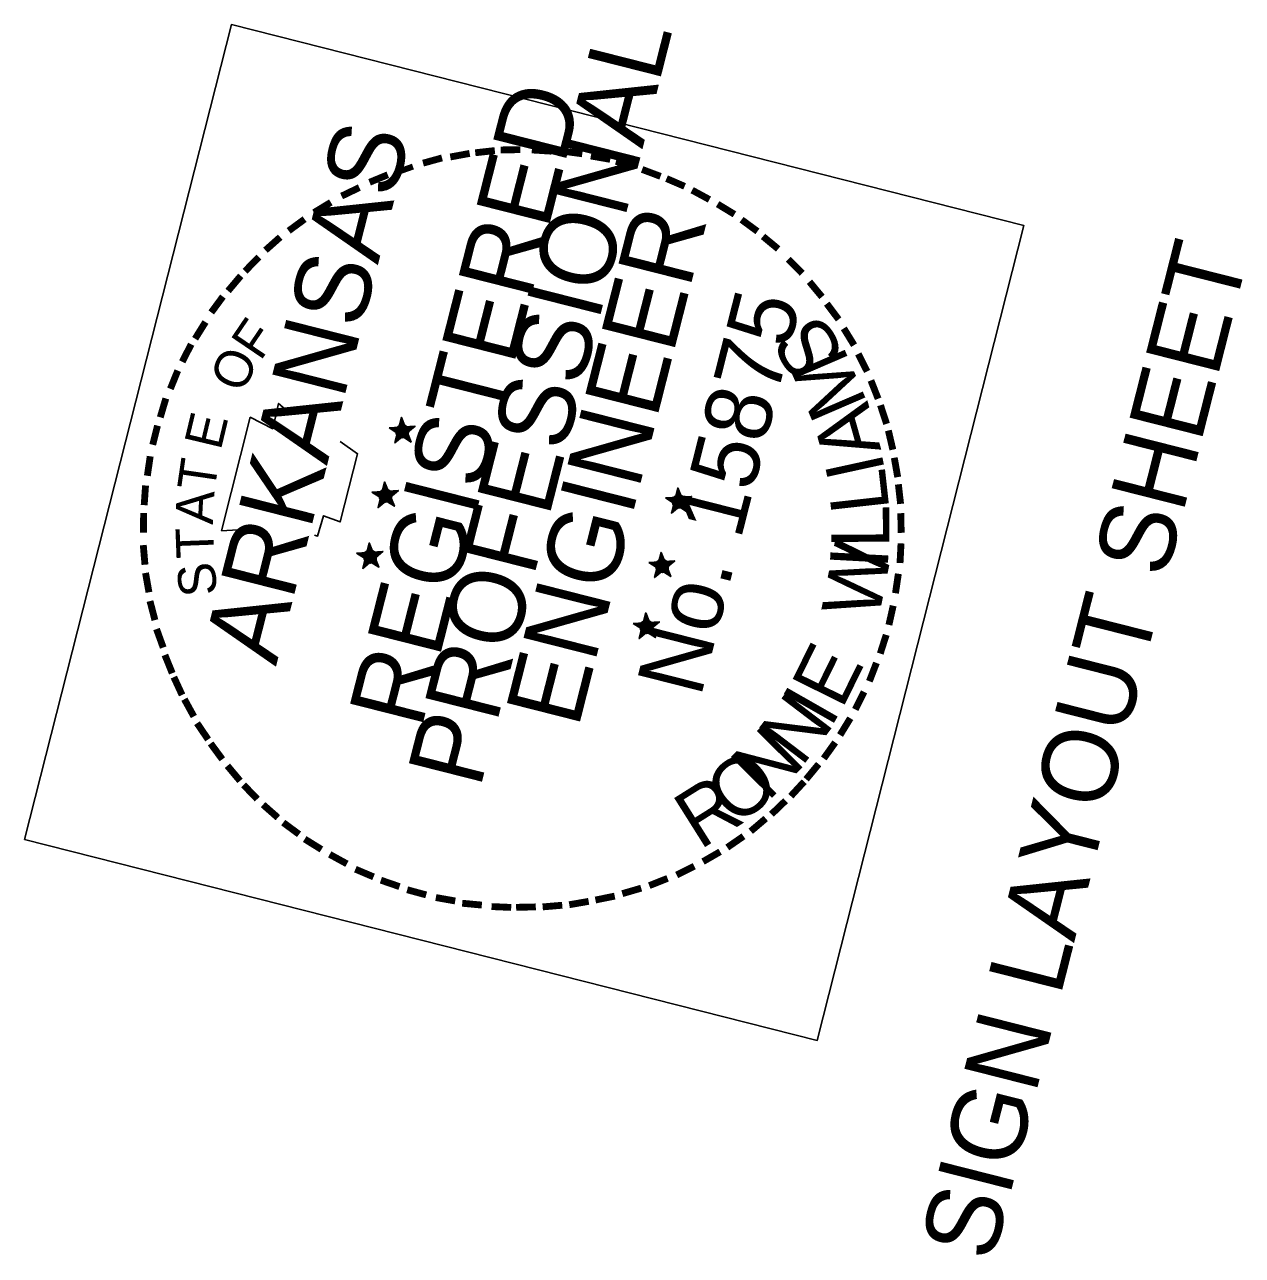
# Model space of a CAD drawing. Extents: x 670002 to 670131, y 737831 to 738002.
# Drawn here: x 670110.58 to 670130.78, y 737963.35 to 737983.77 of the extents above; entities that cross this region are included whole.
import ezdxf

# ---------------------------------------------------------------- set-up
doc = ezdxf.new("R2010")
doc.units = 0
for name, color, linetype in [('R_Border Notes', 7, 'Continuous'), ('R_Border PE', 7, 'Continuous'), ('R_Border Prem', 7, 'Continuous')]:
    doc.layers.add(name, color=color, linetype=linetype)

msp = doc.modelspace()

# ---------------------------------------------------------------- linework, layer by layer
at = {"layer": 'R_Border PE'}
for p, q in [((670116.623, 737977.081), (670116.785, 737977.085)), ((670116.841, 737977.025), (670116.623, 737977.081)), ((670116.623, 737977.081), (670116.782, 737977.073)), ((670116.623, 737977.081), (670116.772, 737977.056)), ((670116.623, 737977.081), (670116.772, 737977.03)), ((670116.623, 737977.081), (670116.769, 737977.018)), ((670116.623, 737977.081), (670116.759, 737977.007)), ((670116.828, 737977.254), (670116.793, 737977.063)), ((670116.828, 737977.254), (670116.814, 737977.071)), ((670116.828, 737977.254), (670116.826, 737977.068)), ((670116.828, 737977.254), (670116.841, 737977.025)), ((670116.828, 737977.254), (670116.849, 737977.107)), ((670116.828, 737977.254), (670116.857, 737977.112)), ((670116.828, 737977.254), (670116.866, 737977.122)), ((670117.055, 737977.106), (670116.841, 737977.025)), ((670117.055, 737977.106), (670116.86, 737977.072)), ((670117.055, 737977.106), (670116.863, 737977.084)), ((670117.055, 737977.106), (670116.882, 737977.06)), ((670117.055, 737977.106), (670116.89, 737977.013)), ((670117.055, 737977.106), (670116.902, 737977.036)), ((670117.055, 737977.106), (670116.908, 737977.008)), ((670116.721, 737976.83), (670116.841, 737977.025)), ((670116.721, 737976.83), (670116.779, 737976.983)), ((670116.721, 737976.83), (670116.79, 737976.974)), ((670116.721, 737976.83), (670116.796, 737976.972)), ((670116.721, 737976.83), (670116.818, 737976.96)), ((670116.721, 737976.83), (670116.831, 737976.957)), ((670116.721, 737976.83), (670116.843, 737976.954)), ((670116.989, 737976.846), (670116.838, 737976.962)), ((670116.989, 737976.846), (670116.841, 737977.025)), ((670116.989, 737976.846), (670116.858, 737976.963)), ((670116.989, 737976.846), (670116.867, 737976.974)), ((670116.989, 737976.846), (670116.89, 737977.013)), ((670116.989, 737976.846), (670116.89, 737976.987)), ((670116.989, 737976.846), (670116.91, 737977.014)), ((670116.55, 737976.183), (670116.515, 737975.993)), ((670116.55, 737976.183), (670116.536, 737976)), ((670116.55, 737976.183), (670116.548, 737975.997)), ((670116.55, 737976.183), (670116.563, 737975.955)), ((670116.55, 737976.183), (670116.571, 737976.036)), ((670116.55, 737976.183), (670116.58, 737976.047)), ((670116.55, 737976.183), (670116.588, 737976.051)), ((670121.413, 737976.085), (670121.379, 737975.9)), ((670121.413, 737976.085), (670121.4, 737975.908)), ((670121.413, 737976.085), (670121.412, 737975.905)), ((670121.413, 737976.085), (670121.427, 737975.862)), ((670121.413, 737976.085), (670121.434, 737975.938)), ((670121.413, 737976.085), (670121.449, 737975.947)), ((670121.413, 737976.085), (670121.457, 737975.952)), ((670116.339, 737976.011), (670116.507, 737976.014)), ((670116.563, 737975.955), (670116.339, 737976.011)), ((670116.339, 737976.011), (670116.498, 737976.003)), ((670116.339, 737976.011), (670116.494, 737975.985)), ((670116.339, 737976.011), (670116.488, 737975.961)), ((670116.339, 737976.011), (670116.491, 737975.947)), ((670116.339, 737976.011), (670116.483, 737975.943)), ((670116.443, 737975.759), (670116.563, 737975.955)), ((670116.443, 737975.759), (670116.495, 737975.914)), ((670116.443, 737975.759), (670116.507, 737975.911)), ((670116.443, 737975.759), (670116.518, 737975.902)), ((670116.443, 737975.759), (670116.54, 737975.889)), ((670116.443, 737975.759), (670116.552, 737975.886)), ((670116.443, 737975.759), (670116.565, 737975.883)), ((670116.713, 737975.781), (670116.56, 737975.891)), ((670116.779, 737976.042), (670116.563, 737975.955)), ((670116.713, 737975.781), (670116.563, 737975.955)), ((670116.779, 737976.042), (670116.579, 737976.015)), ((670116.713, 737975.781), (670116.58, 737975.892)), ((670116.779, 737976.042), (670116.582, 737976.001)), ((670116.713, 737975.781), (670116.589, 737975.903)), ((670116.779, 737976.042), (670116.604, 737975.989)), ((670116.779, 737976.042), (670116.612, 737975.942)), ((670116.713, 737975.781), (670116.612, 737975.942)), ((670116.713, 737975.781), (670116.612, 737975.916)), ((670116.779, 737976.042), (670116.624, 737975.965)), ((670116.779, 737976.042), (670116.63, 737975.938)), ((670116.713, 737975.781), (670116.632, 737975.944)), ((670121.427, 737975.862), (670121.209, 737975.918)), ((670121.209, 737975.918), (670121.37, 737975.915)), ((670121.209, 737975.918), (670121.368, 737975.909)), ((670121.209, 737975.918), (670121.364, 737975.891)), ((670121.209, 737975.918), (670121.358, 737975.867)), ((670121.209, 737975.918), (670121.355, 737975.855)), ((670121.209, 737975.918), (670121.352, 737975.843)), ((670121.307, 737975.667), (670121.427, 737975.862)), ((670121.641, 737975.943), (670121.427, 737975.862)), ((670121.575, 737975.683), (670121.427, 737975.862)), ((670121.641, 737975.943), (670121.444, 737975.903)), ((670121.641, 737975.943), (670121.447, 737975.915)), ((670121.641, 737975.943), (670121.473, 737975.889)), ((670121.641, 737975.943), (670121.48, 737975.842)), ((670121.641, 737975.943), (670121.487, 737975.867)), ((670121.641, 737975.943), (670121.499, 737975.838)), ((670121.307, 737975.667), (670121.364, 737975.814)), ((670121.307, 737975.667), (670121.376, 737975.811)), ((670121.307, 737975.667), (670121.386, 737975.802)), ((670121.307, 737975.667), (670121.404, 737975.797)), ((670121.307, 737975.667), (670121.421, 737975.786)), ((670121.307, 737975.667), (670121.433, 737975.783)), ((670121.575, 737975.683), (670121.423, 737975.792)), ((670121.575, 737975.683), (670121.448, 737975.792)), ((670121.575, 737975.683), (670121.459, 737975.809)), ((670121.575, 737975.683), (670121.476, 737975.824)), ((670121.575, 737975.683), (670121.48, 737975.842)), ((670121.575, 737975.683), (670121.494, 737975.845)), ((670116.294, 737975.172), (670116.258, 737974.981)), ((670116.294, 737975.172), (670116.28, 737974.988)), ((670116.294, 737975.172), (670116.292, 737974.985)), ((670116.294, 737975.172), (670116.307, 737974.943)), ((670116.294, 737975.172), (670116.315, 737975.025)), ((670116.294, 737975.172), (670116.324, 737975.035)), ((670116.294, 737975.172), (670116.331, 737975.04)), ((670116.083, 737975), (670116.251, 737975.002)), ((670116.307, 737974.943), (670116.083, 737975)), ((670116.083, 737975), (670116.242, 737974.992)), ((670116.083, 737975), (670116.239, 737974.979)), ((670116.083, 737975), (670116.233, 737974.955)), ((670116.083, 737975), (670116.234, 737974.936)), ((670116.083, 737975), (670116.226, 737974.931)), ((670116.186, 737974.748), (670116.307, 737974.943)), ((670116.186, 737974.748), (670116.238, 737974.902)), ((670116.186, 737974.748), (670116.251, 737974.899)), ((670116.186, 737974.748), (670116.261, 737974.89)), ((670116.186, 737974.748), (670116.285, 737974.884)), ((670116.186, 737974.748), (670116.296, 737974.875)), ((670116.186, 737974.748), (670116.308, 737974.872)), ((670116.456, 737974.77), (670116.303, 737974.879)), ((670116.522, 737975.03), (670116.307, 737974.943)), ((670116.456, 737974.77), (670116.307, 737974.943)), ((670116.522, 737975.03), (670116.322, 737975.003)), ((670116.456, 737974.77), (670116.323, 737974.881)), ((670116.522, 737975.03), (670116.325, 737974.99)), ((670116.456, 737974.77), (670116.332, 737974.891)), ((670116.522, 737975.03), (670116.348, 737974.978)), ((670116.522, 737975.03), (670116.355, 737974.931)), ((670116.456, 737974.77), (670116.355, 737974.931)), ((670116.456, 737974.77), (670116.355, 737974.905)), ((670116.522, 737975.03), (670116.367, 737974.953)), ((670116.522, 737975.03), (670116.373, 737974.926)), ((670116.456, 737974.77), (670116.375, 737974.932)), ((670121.149, 737974.791), (670120.931, 737974.847)), ((670120.931, 737974.847), (670121.092, 737974.845)), ((670120.931, 737974.847), (670121.09, 737974.839)), ((670120.931, 737974.847), (670121.086, 737974.82)), ((670120.931, 737974.847), (670121.08, 737974.796)), ((670120.931, 737974.847), (670121.077, 737974.784)), ((670120.931, 737974.847), (670121.067, 737974.774)), ((670121.135, 737975.014), (670121.101, 737974.829)), ((670121.135, 737975.014), (670121.122, 737974.837)), ((670121.135, 737975.014), (670121.134, 737974.834)), ((670121.135, 737975.014), (670121.149, 737974.791)), ((670121.135, 737975.014), (670121.156, 737974.867)), ((670121.135, 737975.014), (670121.165, 737974.878)), ((670121.135, 737975.014), (670121.18, 737974.887)), ((670121.363, 737974.873), (670121.149, 737974.791)), ((670121.363, 737974.873), (670121.166, 737974.832)), ((670121.363, 737974.873), (670121.171, 737974.85)), ((670121.363, 737974.873), (670121.19, 737974.826)), ((670121.363, 737974.873), (670121.204, 737974.778)), ((670121.363, 737974.873), (670121.209, 737974.796)), ((670121.363, 737974.873), (670121.214, 737974.768)), ((670121.029, 737974.596), (670121.149, 737974.791)), ((670121.029, 737974.596), (670121.086, 737974.743)), ((670121.029, 737974.596), (670121.098, 737974.74)), ((670121.029, 737974.596), (670121.104, 737974.739)), ((670121.029, 737974.596), (670121.126, 737974.726)), ((670121.029, 737974.596), (670121.139, 737974.723)), ((670121.029, 737974.596), (670121.151, 737974.72)), ((670121.297, 737974.612), (670121.146, 737974.728)), ((670121.297, 737974.612), (670121.149, 737974.791)), ((670121.297, 737974.612), (670121.172, 737974.728)), ((670121.297, 737974.612), (670121.181, 737974.738)), ((670121.297, 737974.612), (670121.198, 737974.779)), ((670121.297, 737974.612), (670121.198, 737974.753)), ((670121.297, 737974.612), (670121.216, 737974.775)), ((670120.675, 737973.835), (670120.837, 737973.839)), ((670120.893, 737973.78), (670120.675, 737973.835)), ((670120.675, 737973.835), (670120.834, 737973.827)), ((670120.675, 737973.835), (670120.829, 737973.809)), ((670120.675, 737973.835), (670120.823, 737973.784)), ((670120.675, 737973.835), (670120.82, 737973.772)), ((670120.675, 737973.835), (670120.811, 737973.762)), ((670120.88, 737974.009), (670120.844, 737973.818)), ((670120.88, 737974.009), (670120.866, 737973.825)), ((670120.88, 737974.009), (670120.878, 737973.822)), ((670120.88, 737974.009), (670120.893, 737973.78)), ((670120.88, 737974.009), (670120.899, 737973.855)), ((670120.88, 737974.009), (670120.908, 737973.866)), ((670120.88, 737974.009), (670120.923, 737973.875)), ((670121.107, 737973.861), (670120.893, 737973.78)), ((670121.107, 737973.861), (670120.91, 737973.821)), ((670121.107, 737973.861), (670120.914, 737973.839)), ((670121.107, 737973.861), (670120.934, 737973.814)), ((670121.107, 737973.861), (670120.947, 737973.766)), ((670121.107, 737973.861), (670120.952, 737973.784)), ((670121.107, 737973.861), (670120.958, 737973.757)), ((670120.772, 737973.585), (670120.893, 737973.78)), ((670120.772, 737973.585), (670120.831, 737973.737)), ((670120.772, 737973.585), (670120.841, 737973.728)), ((670120.772, 737973.585), (670120.847, 737973.727)), ((670120.772, 737973.585), (670120.87, 737973.715)), ((670120.772, 737973.585), (670120.882, 737973.712)), ((670120.772, 737973.585), (670120.894, 737973.708)), ((670121.041, 737973.6), (670120.89, 737973.716)), ((670121.041, 737973.6), (670120.893, 737973.78)), ((670121.041, 737973.6), (670120.915, 737973.716)), ((670121.041, 737973.6), (670120.924, 737973.727)), ((670121.041, 737973.6), (670120.941, 737973.767)), ((670121.041, 737973.6), (670120.941, 737973.742)), ((670121.041, 737973.6), (670120.959, 737973.763))]:
    msp.add_line(p, q, dxfattribs=at)
for points in [[(670114.94, 737977.359), (670114.792, 737977.487), (670114.698, 737977.066), (670114.321, 737977.258), (670113.843, 737975.374)], [(670116.623, 737977.081), (670117.055, 737977.106), (670116.721, 737976.83), (670116.828, 737977.254), (670116.989, 737976.846), (670116.623, 737977.081)], [(670115.385, 737975.299), (670115.439, 737975.285), (670115.537, 737975.622), (670115.815, 737975.519), (670116.102, 737976.652), (670115.812, 737976.855)], [(670116.339, 737976.011), (670116.779, 737976.042), (670116.443, 737975.759), (670116.55, 737976.183), (670116.713, 737975.781), (670116.339, 737976.011)], [(670121.209, 737975.918), (670121.641, 737975.943), (670121.307, 737975.667), (670121.413, 737976.085), (670121.575, 737975.683), (670121.209, 737975.918)], [(670113.843, 737975.374), (670114.386, 737975.404)], [(670116.083, 737975), (670116.522, 737975.03), (670116.186, 737974.748), (670116.294, 737975.172), (670116.456, 737974.77), (670116.083, 737975)], [(670120.931, 737974.847), (670121.363, 737974.873), (670121.029, 737974.596), (670121.135, 737975.014), (670121.297, 737974.612), (670120.931, 737974.847)], [(670120.675, 737973.835), (670121.107, 737973.861), (670120.772, 737973.585), (670120.88, 737974.009), (670121.041, 737973.6), (670120.675, 737973.835)]]:
    msp.add_lwpolyline(points, dxfattribs=at)
for centre, radius in [((670116.843, 737977.024), 0.108), ((670116.843, 737977.024), 0.0975), ((670116.843, 737977.024), 0.0904), ((670116.843, 737977.024), 0.083), ((670116.843, 737977.024), 0.0723), ((670116.843, 737977.024), 0.0672), ((670116.843, 737977.024), 0.0619), ((670116.843, 737977.024), 0.0533), ((670116.843, 737977.024), 0.0467), ((670116.843, 737977.024), 0.0388), ((670116.843, 737977.024), 0.031), ((670116.843, 737977.024), 0.0231), ((670116.843, 737977.024), 0.0185), ((670116.843, 737977.024), 0.00901), ((670116.564, 737975.956), 0.108), ((670116.564, 737975.956), 0.0975), ((670116.564, 737975.956), 0.0904), ((670116.564, 737975.956), 0.083), ((670116.564, 737975.956), 0.0723), ((670116.564, 737975.956), 0.0672), ((670116.564, 737975.956), 0.0619), ((670116.564, 737975.956), 0.0533), ((670116.564, 737975.956), 0.0467), ((670116.564, 737975.956), 0.0388), ((670116.564, 737975.956), 0.031), ((670116.564, 737975.956), 0.0231), ((670116.564, 737975.956), 0.0185), ((670116.564, 737975.956), 0.00901), ((670121.43, 737975.858), 0.108), ((670121.43, 737975.858), 0.0975), ((670121.43, 737975.858), 0.0904), ((670121.43, 737975.858), 0.083), ((670121.43, 737975.858), 0.0723), ((670121.43, 737975.858), 0.0672), ((670121.43, 737975.858), 0.0619), ((670121.43, 737975.858), 0.0533), ((670121.43, 737975.858), 0.0467), ((670121.43, 737975.858), 0.0388), ((670121.43, 737975.858), 0.031), ((670121.43, 737975.858), 0.0231), ((670121.43, 737975.858), 0.0185), ((670121.43, 737975.858), 0.00901), ((670116.308, 737974.945), 0.108), ((670116.308, 737974.945), 0.0975), ((670116.308, 737974.945), 0.0904), ((670116.308, 737974.945), 0.083), ((670116.308, 737974.945), 0.0723), ((670116.308, 737974.945), 0.0672), ((670116.308, 737974.945), 0.0619), ((670116.308, 737974.945), 0.0533), ((670116.308, 737974.945), 0.0467), ((670116.308, 737974.945), 0.0388), ((670116.308, 737974.945), 0.031), ((670116.308, 737974.945), 0.0231), ((670116.308, 737974.945), 0.0185), ((670116.308, 737974.945), 0.00901), ((670121.151, 737974.79), 0.108), ((670121.151, 737974.79), 0.0975), ((670121.151, 737974.79), 0.0904), ((670121.151, 737974.79), 0.083), ((670121.151, 737974.79), 0.0723), ((670121.151, 737974.79), 0.0672), ((670121.151, 737974.79), 0.0619), ((670121.151, 737974.79), 0.0533), ((670121.151, 737974.79), 0.0467), ((670121.151, 737974.79), 0.0388), ((670121.151, 737974.79), 0.031), ((670121.151, 737974.79), 0.0231), ((670121.151, 737974.79), 0.0185), ((670121.151, 737974.79), 0.00901), ((670120.895, 737973.778), 0.108), ((670120.895, 737973.778), 0.0975), ((670120.895, 737973.778), 0.0904), ((670120.895, 737973.778), 0.083), ((670120.895, 737973.778), 0.0723), ((670120.895, 737973.778), 0.0672), ((670120.895, 737973.778), 0.0619), ((670120.895, 737973.778), 0.0533), ((670120.895, 737973.778), 0.0467), ((670120.895, 737973.778), 0.0388), ((670120.895, 737973.778), 0.031), ((670120.895, 737973.778), 0.0231), ((670120.895, 737973.778), 0.0185), ((670120.895, 737973.778), 0.00901)]:
    msp.add_circle(centre, radius, dxfattribs=at)
at = {"layer": 'R_Border Prem'}
msp.add_lwpolyline([(670110.579, 737970.25), (670114.008, 737983.772), (670127.154, 737980.438), (670123.725, 737966.916)], close=True, dxfattribs=at)

# ---------------------------------------------------------------- texts
at = {"layer": 'R_Border Notes'}
msp.add_text('SIGN LAYOUT SHEET', height=1.25, rotation=75.7686, dxfattribs=at).set_placement((670126.637, 737963.215))
at = {"layer": 'R_Border PE'}
for s, height, rotation, p in [('PROFESSIONAL', 1.24999, 75.7686, (670118.131, 737971.076)), ('REGISTERED', 1.25, 75.7686, (670117.156, 737972.064)), ('ARKANSAS', 1.25, 75.7686, (670114.747, 737973.114)), ('-', 1, 15.4369, (670117.233, 737981.085)), ('-', 1, 10.4313, (670117.651, 737981.185)), ('-', 1, 6.3414, (670118.037, 737981.255)), ('-', 1, 0.8918, (670118.423, 737981.305)), ('-', 1, 356.3179, (670118.908, 737981.311)), ('-', 1, 352.3647, (670119.395, 737981.297)), ('-', 1, 350.0987, (670119.846, 737981.222)), ('-', 0.875, 19.4438, (670116.814, 737980.985)), ('-', 1, 345.7092, (670120.233, 737981.143)), ('-', 1, 339.2857, (670120.629, 737981.029)), ('-', 1, 22.4207, (670116.393, 737980.776)), ('-', 1, 336.7638, (670121.019, 737980.886)), ('-', 1, 25.6483, (670115.95, 737980.553)), ('-', 1, 331.5312, (670121.414, 737980.714)), ('-', 1, 31.3471, (670115.529, 737980.292)), ('-', 1, 328.6366, (670121.822, 737980.495)), ('-', 1, 36.2983, (670115.14, 737980.004)), ('ENGINEER', 1.25, 75.7686, (670119.758, 737972.075)), ('-', 1, 323.6572, (670122.194, 737980.259)), ('-', 1, 41.6312, (670114.786, 737979.7)), ('-', 1, 320.3883, (670122.534, 737979.998)), ('-', 1, 45.4094, (670114.469, 737979.368)), ('-', 1, 314.8398, (670122.929, 737979.647)), ('-', 1, 49.8896, (670114.211, 737979.059)), ('-', 1, 309.6138, (670123.261, 737979.305)), ('No. 15875', 1.1, 75.7686, (670121.79, 737972.59)), ('-', 1, 53.6236, (670113.95, 737978.719)), ('-', 1, 307.0223, (670123.54, 737978.956)), ('F', 0.625, 55.8392, (670114.49, 737978.176)), ('-', 1, 58.1047, (670113.703, 737978.305)), ('S', 0.962, 121.462, (670124.213, 737978.277)), ('-', 1, 301.5339, (670123.806, 737978.58)), ('-', 1, 62.9734, (670113.51, 737977.948)), ('O', 0.625, 66.2201, (670114.204, 737977.636)), ('M', 0.962, 113.3256, (670124.565, 737977.488)), ('-', 1, 296.8536, (670124.035, 737978.186)), ('-', 1, 67.9303, (670113.332, 737977.528)), ('-', 1, 291.5049, (670124.235, 737977.781)), ('-', 1, 73.5116, (670113.182, 737977.089)), ('A', 0.962, 105.7601, (670124.789, 737976.716)), ('E', 0.625, 76.6009, (670113.83, 737976.693)), ('-', 1, 288.0176, (670124.389, 737977.394)), ('-', 1, 75.9548, (670113.064, 737976.649)), ('-', 1, 283.1254, (670124.516, 737977.007)), ('-', 1, 81.6654, (670112.988, 737976.171)), ('T', 0.625, 81.7913, (670113.727, 737976.01)), ('I', 0.962, 102.3343, (670124.857, 737976.358)), ('-', 1, 280.0202, (670124.613, 737976.576)), ('L', 0.962, 96.339, (670124.924, 737975.724)), ('-', 1, 85.9879, (670112.943, 737975.712)), ('-', 1, 276.487, (670124.681, 737976.159)), ('A', 0.625, 86.9817, (670113.7, 737975.469)), ('-', 1, 89.3987, (670112.935, 737975.276)), ('L', 0.962, 90.3438, (670124.923, 737975.087)), ('-', 1, 271.2428, (670124.724, 737975.716)), ('T', 0.625, 92.1721, (670113.724, 737974.927)), ('W', 0.962, 78.7816, (670124.736, 737973.873)), ('-', 1, 94.9446, (670112.965, 737974.784)), ('-', 1, 267.0543, (670124.733, 737975.243)), ('S', 0.625, 97.3626, (670113.784, 737974.325)), ('I', 0.962, 86.9179, (670124.893, 737974.724)), ('-', 1, 100.0758, (670113.032, 737974.361)), ('-', 1, 261.5852, (670124.698, 737974.775)), ('-', 1, 104.5604, (670113.129, 737973.93)), ('-', 1, 257.3603, (670124.622, 737974.272)), ('-', 1, 109.8321, (670113.261, 737973.51)), ('-', 1, 252.2868, (670124.52, 737973.82)), ('E', 0.962, 63.7221, (670124.135, 737972.394)), ('-', 1, 112.0003, (670113.408, 737973.099)), ('-', 1, 248.884, (670124.369, 737973.375)), ('-', 1, 114.7192, (670113.566, 737972.756)), ('-', 1, 118.7308, (670113.753, 737972.425)), ('N', 0.962, 52.7308, (670123.464, 737971.439)), ('I', 0.962, 60.2962, (670123.946, 737972.083)), ('-', 1, 243.3241, (670124.184, 737972.926)), ('-', 1, 124.1916, (670113.975, 737972.078)), ('-', 1, 238.5668, (670123.976, 737972.514)), ('N', 0.962, 45.1654, (670122.901, 737970.865)), ('-', 1, 126.3827, (670114.204, 737971.762)), ('-', 1, 234.3298, (670123.745, 737972.134)), ('O', 0.962, 38.8847, (670122.38, 737970.447)), ('-', 1, 130.001, (670114.486, 737971.426)), ('-', 1, 230.3687, (670123.49, 737971.793)), ('-', 1, 133.8392, (670114.757, 737971.145)), ('R', 0.962, 32.1757, (670121.776, 737970.068)), ('-', 1, 227.3389, (670123.265, 737971.515)), ('-', 1, 138.6399, (670115.079, 737970.863)), ('-', 1, 223.8583, (670122.976, 737971.214)), ('-', 1, 143.5428, (670115.408, 737970.612)), ('-', 1, 220.4149, (670122.666, 737970.931)), ('-', 1, 214.7024, (670122.331, 737970.655)), ('-', 1, 148.163, (670115.756, 737970.382)), ('-', 1, 151.2295, (670116.163, 737970.156)), ('-', 1, 209.9924, (670121.973, 737970.411)), ('-', 1, 156.9698, (670116.572, 737969.962)), ('-', 1, 206.4867, (670121.566, 737970.179)), ('-', 1, 160.9549, (670116.979, 737969.814)), ('-', 1, 201.662, (670121.156, 737969.986)), ('-', 1, 164.8308, (670117.398, 737969.688)), ('-', 1, 169.9644, (670117.847, 737969.6)), ('-', 1, 191.4974, (670120.348, 737969.701)), ('-', 1, 196.2157, (670120.755, 737969.83)), ('-', 1, 174.7165, (670118.257, 737969.541)), ('-', 1, 177.4835, (670118.726, 737969.506)), ('-', 1, 181.2264, (670119.109, 737969.519)), ('-', 1, 184.856, (670119.523, 737969.549)), ('-', 1, 189.8329, (670119.927, 737969.614))]:
    msp.add_text(s, height=height, rotation=rotation, dxfattribs=at).set_placement(p)

doc.saveas('drawing.dxf')
